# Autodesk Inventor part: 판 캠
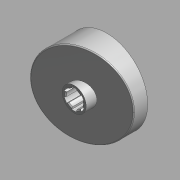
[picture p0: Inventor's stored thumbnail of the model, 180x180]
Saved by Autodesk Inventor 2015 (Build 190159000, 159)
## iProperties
Created: 2015-11
Part Number: 판 캠
Document SubType Name: 모델링
Designer: mdu
Material: 강철, 연강
Density: 1 g/cm^3
Appearance: 알루미늄 - 평지
변환 표준: STEP AP214IS
파일 이름: C:\Users\SeoGD\Desktop\?쒗뿕\??stp
전처리기: Build: 253, Release: 2010 SP1 - Date: Wed 07/29/2009
전송 단위: 밀리미터
불확실성: 0.01
Author: mdu
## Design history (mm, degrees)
node "작업 평면4"
sketch "스케치1"
  geometry: C1 r 44.5 at (0, 0); 1 further point
  constraints: 1 centre point, 1 coincident
  dimensions: "d25" = 89 diameter of C1
extrude "돌출1" new body sketch "스케치1" distance "d1" = 40; taper "d2" = 0 deg
sketch "스케치2"
  geometry: L1 (-44.5, 15)-(44.5, 38.847); L2 (-44.5, 0)-(-44.5, 40) reference; L3 (-44.5, 40)-(44.5, 40) reference; L4 (44.5, 0)-(44.5, 40) reference; 1 further point
  constraints: 2 end point, 2 point on line
  dimensions: "d26" = 15 distance of L2.start L1.start; "d27" = 75 deg angle of L1 L2
extrude "돌출2" cut sketch "스케치2" stored distance "d5" = 40; taper "d6" = 0 deg
node "작업 평면1"
sketch "스케치3"
  geometry: C1 r 13 at (0, 0); 1 further point
  constraints: 1 centre point, 1 coincident
  dimensions: "d9" = 26 diameter of C1
extrude "돌출3" join sketch "스케치3" distance "d10" = 38; taper "d11" = 0 deg
hole "구멍1" diameter "d14" = 18; stored, may be unused: countersink angle "d18" = 90 deg, drill point angle "d20" = 118 deg; dims "d12" = 10, "d13" = 10, "d15" = 6, "d16" = 4, "d17" = 2, "d19" = 8
feature "쉘2" dims "d29" = 5
sketch "스케치6"
  geometry: C1 r 17.5 at (0, 0); C2 r 14 at (0, 0) reference; 1 further point
  constraints: 1 centre point, 1 coincident
  dimensions: "d28" = 35 diameter of C1
extrude "돌출4" join sketch "스케치6" stored distance "d30" = 38; taper "d31" = 0 deg
fillet "모깎기1" dims "d32" = 3
chamfer "모따기1" distance "d21" = 1; stored, may be unused: second distance "d22" = 2, angle "d23" = 45 deg
sketch "스케치7"
  geometry: L1 (-12.374, 12.374)-(-27.931, 27.931); A1 r 39.5 centre (0, 0) between (-27.931, 27.931) and (0, 39.5) reference; 2 further points
  constraints: 2 end point, 2 point on circle, 1 point on line, 1 vertical alignment, 2 other
  dimensions: "d33" = 45 deg dimension on point (0, 0) L1.start A1.end
feature "리브1" sketch "스케치7" dims "d34" = 5, "d35" = 1, "d36" = 0
fillet "모깎기2" dims "d37" = 3
sketch "스케치8"
  geometry: L1 (2.5, 10.712)-(2.5, 8.646); L2 (-2.5, 10.712)-(-2.5, 8.646); A1 r 11 centre (0, 0) between (2.5, 10.712) and (-2.5, 10.712); A2 r 9 centre (0, 0) between (2.5, 8.646) and (-2.5, 8.646) reference; 1 further point
  constraints: 4 end point, 4 point on circle, 2 parallel, 1 centre point, 1 coincident, 1 vertical
  dimensions: "d41" = 22 diameter of A1; "d42" = 5 distance between parallel lines of L1 L2
extrude "돌출5" cut sketch "스케치8" stored distance "d43" = 38; taper "d44" = 0 deg
fillet "모깎기3" dims "d48" = 1
node "솔리드1"
node "솔리드 본체"
node "곡면 본체"
pattern_circular "원형 패턴1" dims angle "d39" = 360 deg
pattern_circular "원형 패턴2" dims angle "d46" = 360 deg
node "솔리드2"
